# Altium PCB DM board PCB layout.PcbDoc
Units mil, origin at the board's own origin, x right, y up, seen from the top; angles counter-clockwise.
Board outline 4730 x 3600 mil, 4 copper layers (Top Layer, InternalPlane1, InternalPlane2, Bottom Layer); 96 components, 92 nets, 343 pads, 111 vias.
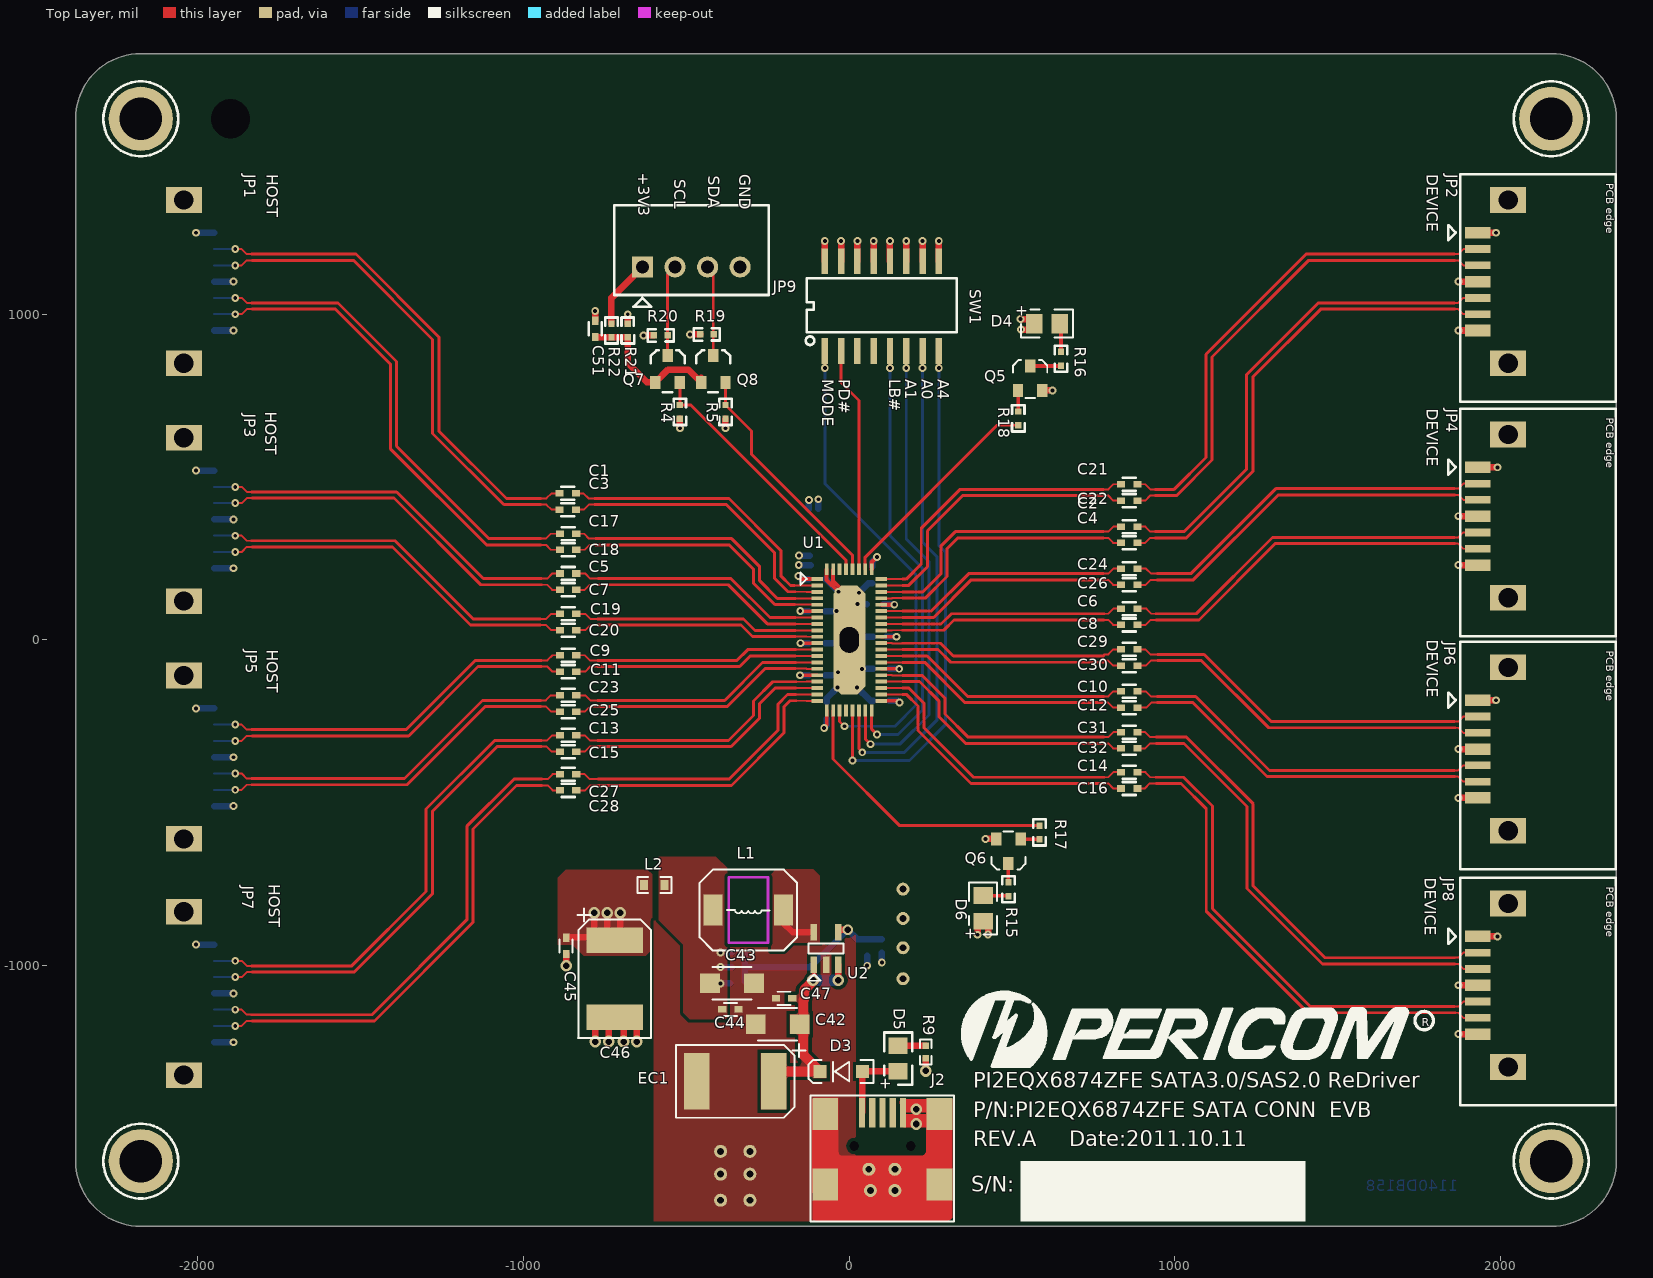
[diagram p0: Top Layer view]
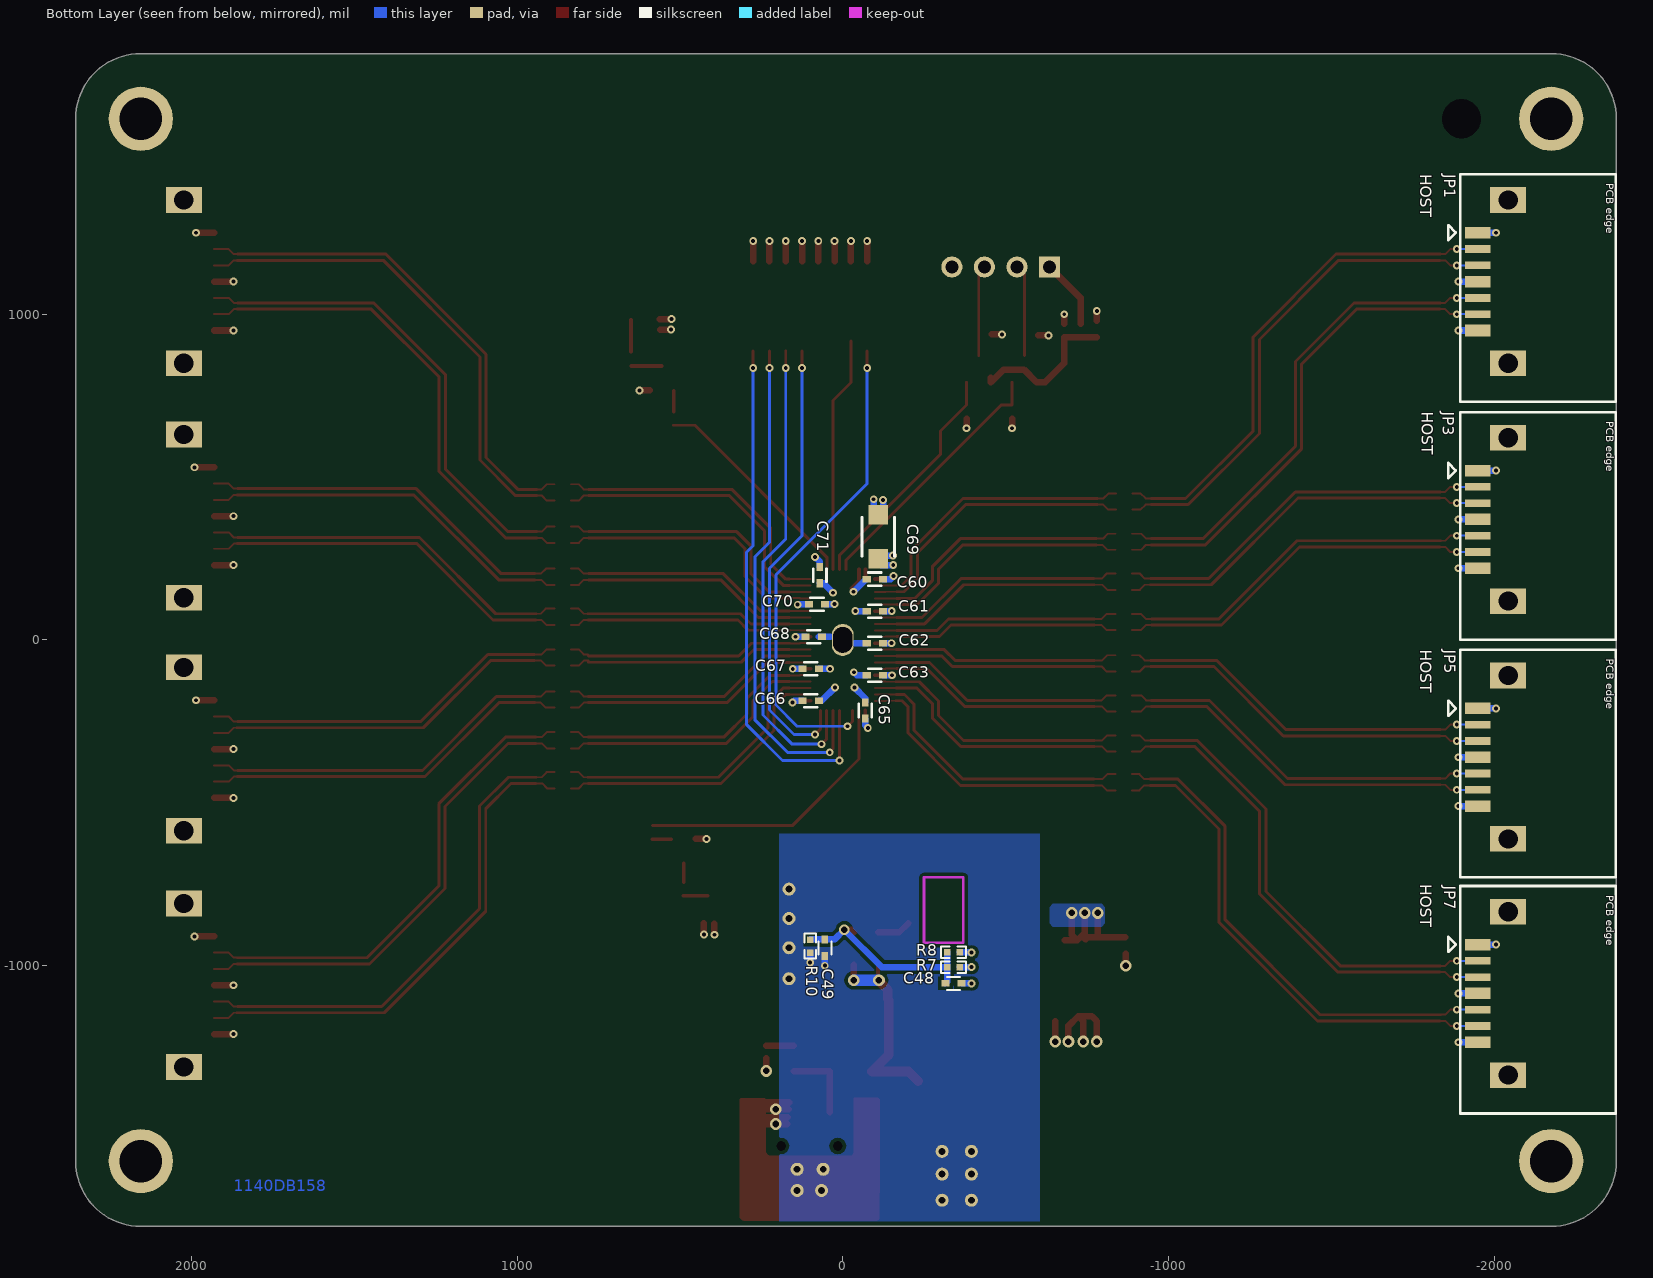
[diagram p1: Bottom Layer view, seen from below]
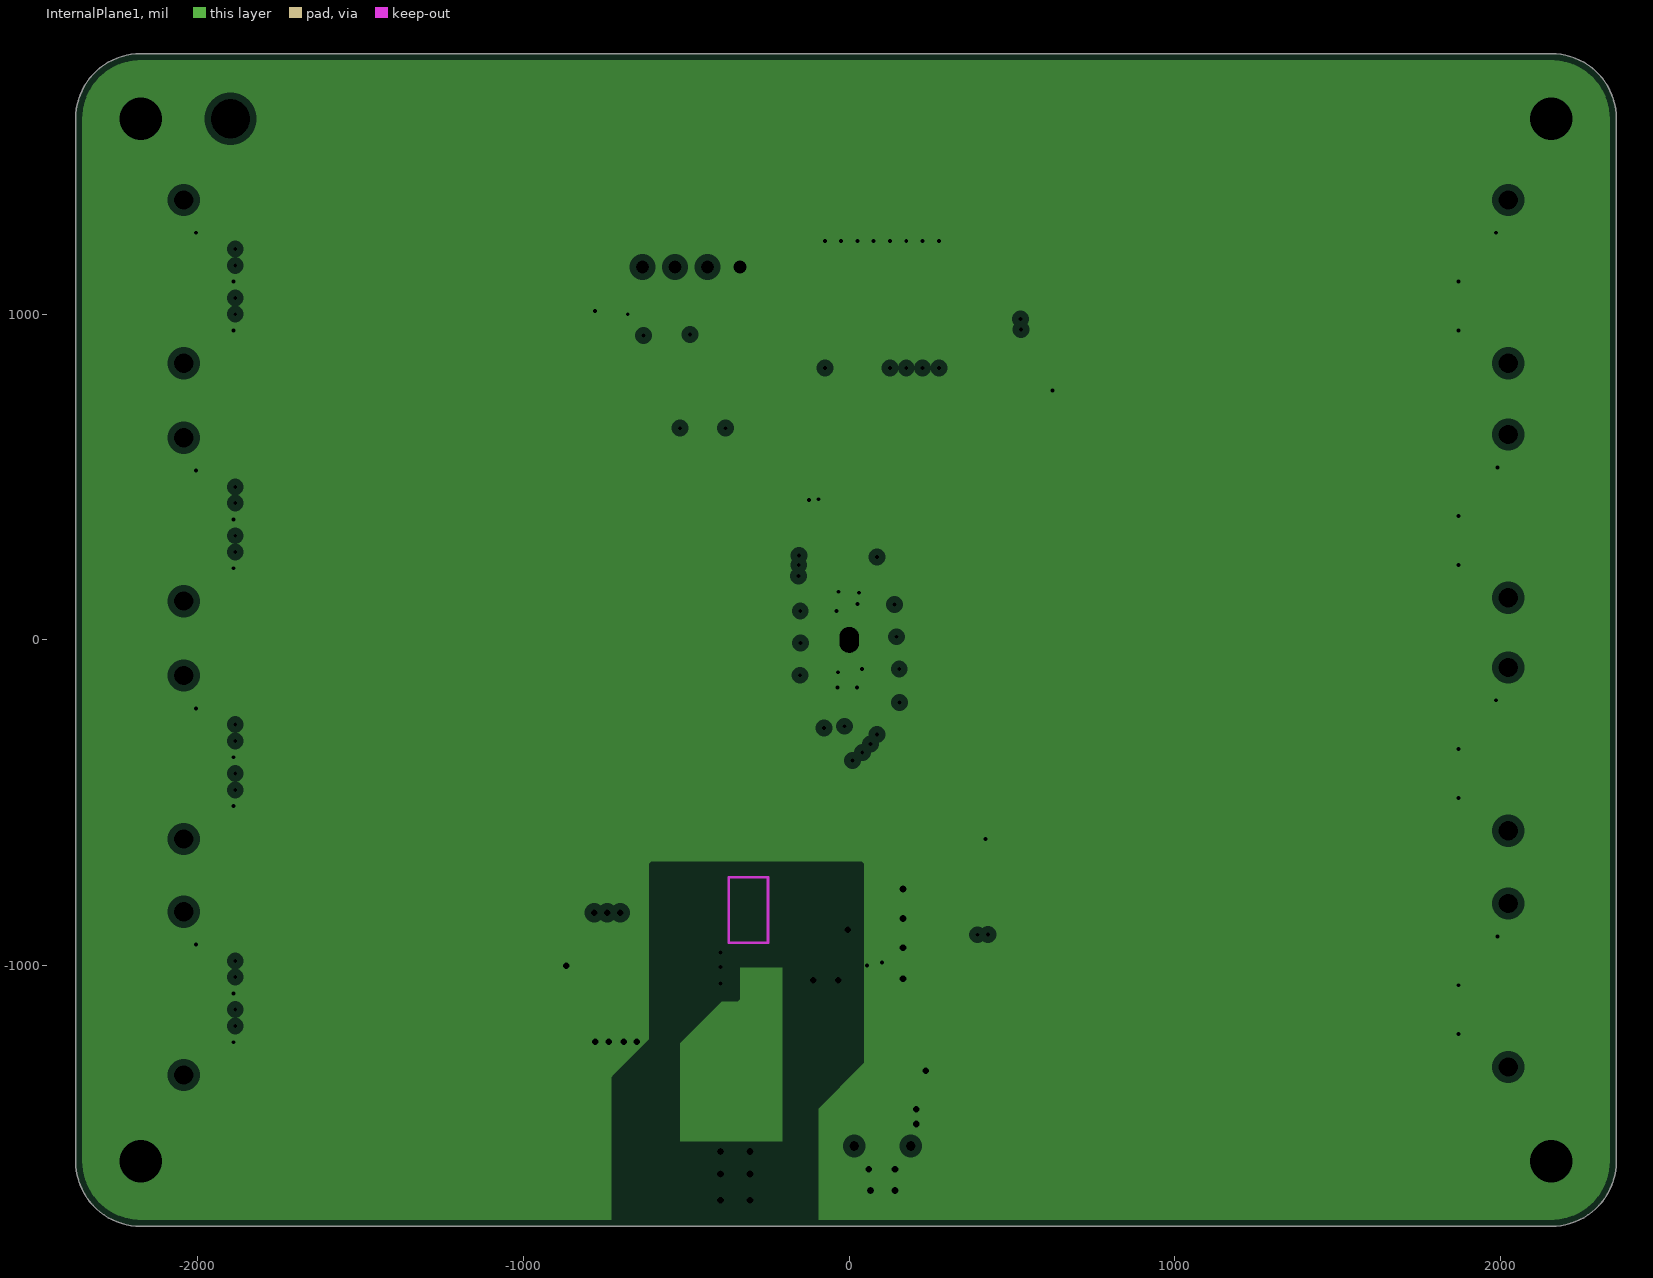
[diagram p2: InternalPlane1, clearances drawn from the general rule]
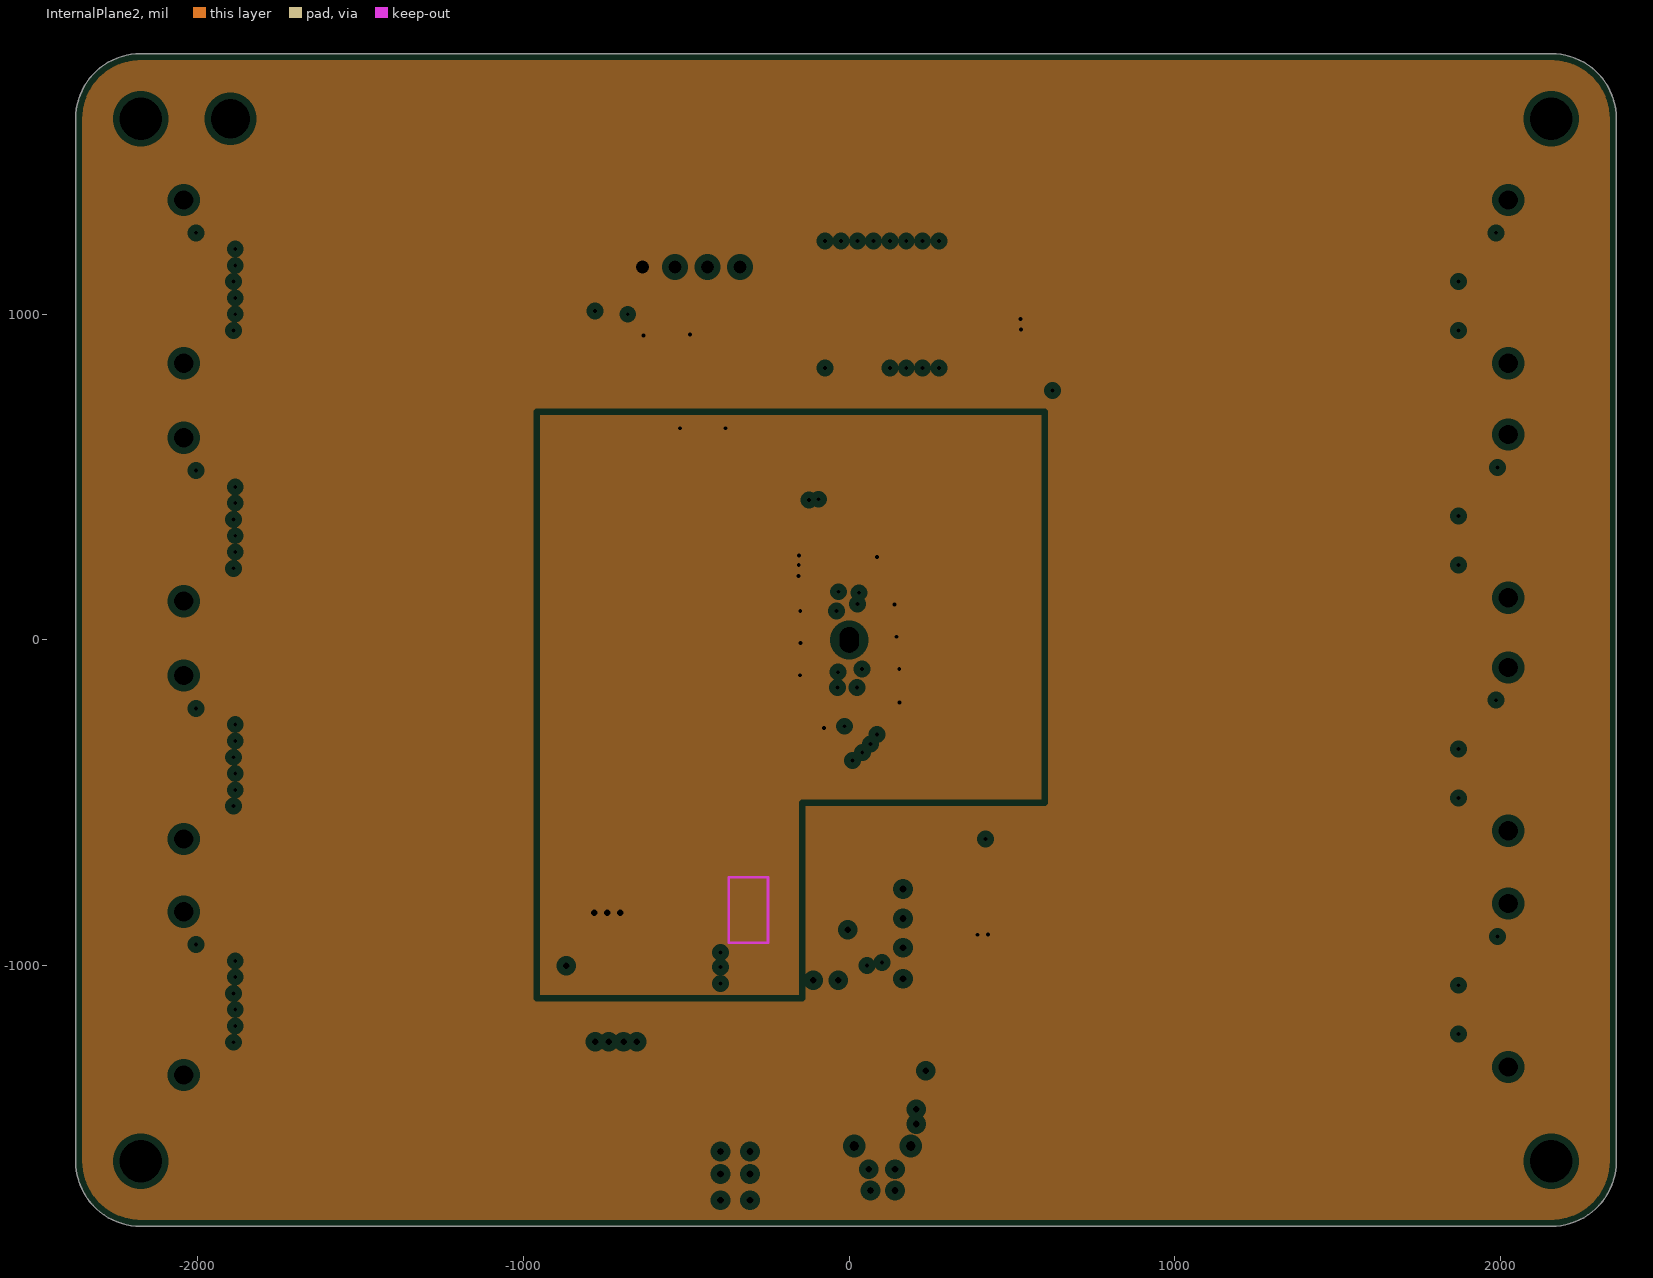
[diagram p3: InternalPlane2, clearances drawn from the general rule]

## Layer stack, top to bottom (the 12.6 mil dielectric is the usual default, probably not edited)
Top Layer: signal copper 1.4
Dielectric: core 12.6, FR-4, Dk 4.8
InternalPlane1: plane copper 1.4, net GND
Dielectric: prepreg 12.6, FR-4, Dk 4.8
InternalPlane2: plane copper 1.4, net +3V3
Dielectric: core 12.6, FR-4, Dk 4.8
Bottom Layer: signal copper 1.4

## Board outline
-2175,-1800 2155,-1800 ccw(c2155,-1600) 2355,-1600 2355,1600 ccw(c2155,1600) 2155,1800 -2175,1800 ccw(c-2175,1600) -2375,1600 -2375,-1600 ccw(c-2175,-1600)

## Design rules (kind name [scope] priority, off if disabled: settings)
Clearance [All] p1: gap=5
ComponentClearance [All] p1: gap=0 collisioncheckmode=3 verticalgap=0
DiffPairsRouting [All] p1: maxlimit=10 minlimit=10 mostfreqgap=10 maxuncoupledlength=500
HoleSize [All] p1: absolutevalues=TRUE maxlimit=500 minlimit=1 maxpercent=80.000 minpercent=20.000
PlaneClearance [All] p1: clearance=20
PlaneConnect [All] p1: planeconnectstyle=Direct reliefexpansion=20 reliefentries=4 reliefconductorwidth=10 reliefairgap=10
PolygonConnect [All] p1: connectstyle=Direct reliefconductorwidth=10 reliefentries=4 polygonreliefangle="90 Angle"
RoomDefinition "PI2EQX6874ZFE TestBoard" [InComponentClass('PI2EQX6874ZFE TestBoard')] p1: confinementstyle=ConfineIn formatcopy=TRUE lockcomponents=FALSE outline -3785,-2755 7974.61,-2755 7974.61,2490 -3785,2490
RoutingVias [All] p1: holewidth=28 width=50 viastyle="Through Hole" minholewidth=8 minwidth=10 maxholewidth=28 maxwidth=50
SolderMaskExpansion [All] p1: expansion=4
TestPointUsage [All] p1: valid=0 allowmultiple=FALSE
Testpoint [All] p1: side=15 testpointundercomponent=TRUE minsize=40 maxsize=100 preferedsize=60 minholesize=0 maxholesize=40 preferedholesize=32 testpointgrid=1 style=1023 order=0-112345678
Width [All] p1: maxlimit=160 minlimit=6 preferedwidth=10
14 further rules are at their usual default settings.

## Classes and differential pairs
differential pair NewDifferentialPair24: +B3TX_P -B3TX_N
differential pair NewDifferentialPair23: +B3RX_P -B3RX_N
differential pair NewDifferentialPair22: +B2TX_P -B2TX_N
differential pair NewDifferentialPair21: +B2RX_P -B2RX_N
differential pair NewDifferentialPair20: +B1TX_P -B1TX_N
differential pair NewDifferentialPair19: +B1RX_P -B1RX_N
differential pair NewDifferentialPair18: +B0TX_P -B0TX_N
differential pair NewDifferentialPair17: +B0RX_P -B0RX_N
differential pair NewDifferentialPair8: +A3TX_P -A3TX_N
differential pair NewDifferentialPair7: +A3RX_P -A3RX_N
differential pair NewDifferentialPair6: +A2TX_P -A2TX_N
differential pair NewDifferentialPair5: +A2RX_P -A2RX_N
differential pair NewDifferentialPair4: +A1TX_P -A1TX_N
differential pair NewDifferentialPair3: +A1RX_P -A1RX_N
differential pair NewDifferentialPair2: +A0TX_P -A0TX_N
differential pair NewDifferentialPair1: +A0RX_P -A0RX_N
differential pair NewDifferentialPair33: +A0RXC_N -A0RXC_P
differential pair NewDifferentialPair34: +A0TXC_N -A0TXC_P
differential pair NewDifferentialPair35: +A1RXC_N -A1RXC_P
differential pair NewDifferentialPair36: +A1TXC_N -A1TXC_P
differential pair NewDifferentialPair37: +A2RXC_N -A2RXC_P
differential pair NewDifferentialPair38: +A2TXC_N -A2TXC_P
differential pair NewDifferentialPair39: +A3RXC_N -A3RXC_P
differential pair NewDifferentialPair40: +A3TXC_N -A3TXC_P
differential pair NewDifferentialPair41: +B0RXC_N -B0RXC_P
differential pair NewDifferentialPair42: +B0TXC_N -B0TXC_P
differential pair NewDifferentialPair43: +B1RXC_N -B1RXC_P
differential pair NewDifferentialPair44: +B1TXC_N -B1TXC_P
differential pair NewDifferentialPair45: +B2RXC_N -B2RXC_P
differential pair NewDifferentialPair46: +B2TXC_N -B2TXC_P
differential pair NewDifferentialPair9: +B3RXC_N -B3RXC_P
differential pair NewDifferentialPair10: +B3TXC_N -B3TXC_P

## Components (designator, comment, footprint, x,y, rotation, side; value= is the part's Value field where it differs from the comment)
C1 "10n" CC_0402 -864,450 r0 top
C2 "10n" CC_0402 859.5,348 r0 top
C3 "10n" CC_0402 -864,400 r0 top
C4 "10n" CC_0402 859.5,298 r0 top
C5 "10n" CC_0402 -863,204 r0 top
C6 "10n" CC_0402 859.5,96 r0 top
C7 "10n" CC_0402 -863,154 r0 top
C8 "10n" CC_0402 859.5,46 r0 top
C9 "10n" CC_0402 -863,-47 r0 top
C10 "10n" CC_0402 859.5,-158 r0 top
C11 "10n" CC_0402 -863,-97 r0 top
C12 "10n" CC_0402 859.5,-208 r0 top
C13 "10n" CC_0402 -863,-293 r0 top
C14 "10n" CC_0402 859.5,-406 r0 top
C15 "10n" CC_0402 -863,-343 r0 top
C16 "10n" CC_0402 859.5,-456 r0 top
C17 "10n" CC_0402 -863,326 r0 top
C18 "10n" CC_0402 -863,277 r0 top
C19 "10n" CC_0402 -863,80 r0 top
C20 "10n" CC_0402 -863,30 r0 top
C21 "10n" CC_0402 859.5,478 r0 top
C22 "10n" CC_0402 859.5,428 r0 top
C23 "10n" CC_0402 -863,-170 r0 top
C24 "10n" CC_0402 859.5,219 r0 top
C25 "10n" CC_0402 -863,-220 r0 top
C26 "10n" CC_0402 859.5,169 r0 top
C27 "10n" CC_0402 -863,-412 r0 top
C28 "10n" CC_0402 -863,-462 r0 top
C29 "10n" CC_0402 859.5,-29 r0 top
C30 "10n" CC_0402 859.5,-79 r0 top
C31 "10n" CC_0402 859.5,-283 r0 top
C32 "10n" CC_0402 859.5,-333 r0 top
C42 "4.7u" CAP@CC_1206 -220,-1179.33 r180 top
C43 "10u" CAP@CC_1206 -360,-1054.33 r0 top
C44 "0.1u" CAP@CC_0402 -365,-1134.33 r0 top
C45 "0.1u" CAP@CC_0402 -869,-939 r90 top
C46 "100u" CAP@CT_7343 -720,-1040 r90 top locked
C47 "0.1u" CAP@CC_0402 -200,-1100 r180 top
C48 "12pF" CAP@CC_0402 -340,-1054.33 r0 bottom
C49 "NP" CAP@CC_0402 55,-945 r270 bottom
C51 "100n" CAP@CC_0402 -780,955 r90 top
C60 "0.1u" CC_0402 -98.82,187.01 r0 bottom
C61 "0.1u" CC_0402 -98.82,88.58 r0 bottom
C62 "0.1u" CC_0402 -98.82,-9.84 r0 bottom
C63 "0.1u" CC_0402 -98.82,-108.27 r0 bottom
C65 "0.1u" CC_0402 -69.29,-216.54 r90 bottom
C66 "0.1u" CC_0402 98.03,-187.01 r180 bottom
C67 "0.1u" CC_0402 98.03,-88.58 r180 bottom
C68 "0.1u" CC_0402 89,10 r180 bottom
C69 "10u_1206" CC_1206 -109,317 r90 bottom
C70 "0.1u" CC_0402 79,110 r180 bottom (schematic designator C68)
C71 "0.1u" CC_0402 70,199 r270 bottom (schematic designator C68)
D3 "B0520LW" D_SOD_123 -25,-1325 r180 top
D4 "LED" LED@LD0805 607,971 r0 top
D5 "LED" LED@LD0805 150,-1285 r90 top
D6 "LED" LED@LD0805 411,-824 r90 top
EC1 "100uF" CAP@CT_7343 -350,-1355 r0 top
J2 "Mini USB 2.0 Type B Female" USB_B_MINI@USB_B_MINI 102,-1760 r90 top (schematic designator J1)
JP1 "CON_SATA_SMT" CON_SATA_SMT -1950,950 r90 bottom
JP2 "CON_SATA_SMT" CON_SATA_SMT 1930,950 r90 top
JP3 "CON_SATA_SMT" CON_SATA_SMT -1950,220 r90 bottom
JP4 "CON_SATA_SMT" CON_SATA_SMT 1930,230 r90 top
JP5 "CON_SATA_SMT" CON_SATA_SMT -1950,-510 r90 bottom
JP6 "CON_SATA_SMT" CON_SATA_SMT 1930,-485 r90 top
JP7 "CON_SATA_SMT" CON_SATA_SMT -1950,-1235 r90 bottom
JP8 "CON_SATA_SMT" CON_SATA_SMT 1930,-1210 r90 top
JP9 "CONN_4P" "I2C Device" -635,1145 r0 top
L1 "2.2uH" INDUCTORS-Power -310,-829.33 r180 top
L2 "BL1005LL680" FB@LF0603 -599,-752 r180 top
Q5 "MMBT3904" Q(NPN)@SOT23 518,766 r0 top
Q6 "MMBT3904" Q(NPN)@SOT23 526,-611 r180 top
Q7 "2SK3018@SOT-23" SOT-23 -595,795 r0 top
Q8 "2SK3018@SOT-23" SOT-23 -455,795 r0 top
R4 "4.7K" RES@R_0402#1 -520,700 r90 top
R5 "4.7K" RES@R_0402#1 -380,700 r90 top
R7 "280k" RES@R_0402#2 -340,-1004.33 r0 bottom
R8 "680k" RES@R_0402#2 -340,-959.33 r0 bottom
R9 "510" RES@R_0402#2 235,-1265 r90 top
R10 "200K" RES@R_0402#2 100,-940 r270 bottom
R15 "470" R_0402 489,-765 r270 top
R16 "470" R_0402 650,863 r90 top
R17 "470" R_0402 584,-591 r270 top
R18 "470" R_0402 519,680 r90 top
R19 "10k" R_0402 -437,938 r0 top
R20 "10k" R_0402 -579,935 r0 top
R21 "27k" RES@R_0402#1 -680,950 r90 top
R22 "10k" RES@R_0402#1 -730,950 r90 top
SW1 "CHS-08TA" CHS-08TA@CHS-08TA 100,1025 r0 top
U1 "PI2EQX6874ZFE@TQFN56" TQFN56 0,0 r90 top locked
U2 "LM3674" SOT23-5 -71,-947.33 r180 top locked
? "" "Lable Hole" -1900,1600 r0 top
? "" PSC_LOGO3 380,-1295 r0 top
? "" HOLE5M3M3 2155,-1600 r0 top
? "" HOLE5M3M3 -2175,-1600 r0 top
? "" HOLE5M3M3 -2175,1600 r0 top
? "" HOLE5M3M3 2155,1600 r0 top

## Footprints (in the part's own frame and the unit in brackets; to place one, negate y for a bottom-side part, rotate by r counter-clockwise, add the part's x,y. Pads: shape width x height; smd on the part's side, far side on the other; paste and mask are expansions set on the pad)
CAP@CC_0402 [mil]
  rect 25x20 smd: 1(-25,0) 2(25,0)
  silkscreen extent -20,-20 20,20
CAP@CC_1206 [mil]
  rect 60x60 smd: 1(-67.5,0) 2(67.5,0)
  silkscreen extent -60,-50 60,50
CAP@CT_7343 [mm]
  rect 2x4.4 smd: 1(3,0) 2(-3,0)
  silkscreen extent -4.63,-2.84 5.48,2.9
CC_0402 [mil]
  rect 25x20 smd: 1(-25,0) 2(25,0)
  silkscreen extent -20,-20 20,20
CC_1206 [mil]
  rect 60x60 smd: 1(-67.5,0) 2(67.5,0)
  silkscreen extent -60,-50 60,50
CHS-08TA@CHS-08TA [mm] "CHS-08TA"
  rect 0.5x2 smd: 1(-4.445,-3.5) 2(-3.175,-3.5) 3(-1.905,-3.5) 4(-0.635,-3.5) 5(0.635,-3.5) 6(1.905,-3.5) 7(3.175,-3.5) 8(4.445,-3.5) 9(4.445,3.5) 10(3.175,3.5) 11(1.905,3.5) 12(0.635,3.5) 13(-0.635,3.5) 14(-1.905,3.5) 15(-3.175,3.5) 16(-4.445,3.5)
  silkscreen extent -5.93,-3.04 5.85,2.16
CON_SATA_SMT [mm] "SATA7PIN, BODY 17.74x11.9, 7x1, PITCH 1.27"
  rect 2x2.8 hole 1.5: 0(-2.56,-2.36) 0(10.18,-2.36)
  rect 0.9x2 smd: 1(7.62,0.003) 4(3.81,0.003) 7(0,0.003)
  rect 0.6x2 smd: 2(6.35,0.003) 3(5.08,0.003) 5(2.54,0.003) 6(1.27,0.003)
  silkscreen extent -5.56,-10.76 12.18,2.31
D_SOD_123 [mil]
  rect 40x40 smd: 1(-65,0) 2(65,0)
  silkscreen extent -100,-35 100,35
FB@LF0603 [mm]
  rect 0.635x0.8 smd: 1(-0.8,0) 2(0.8,0)
  silkscreen extent -1.34,-0.62 1.3,0.62
HOLE5M3M3 [mm] "HOLE, Plated"
  round 5 hole 3.3: 0(0,0)
  silkscreen extent -2.92,-2.92 2.92,2.92
"I2C Device" [mil]
  rect 65x65 hole 40: 1(0,0)
  round 65 hole 40: 2(100,0) 3(200,0) 4(300,0)
  silkscreen extent -87,-86 387,190
INDUCTORS-Power [mm]
  rect 1.5x2.4 smd: 1(-2.75,0) 2(2.75,0)
  Keep-Out Layer lines w0.203: 1.53,2.55 -1.54,2.55 -1.54,-2.55 1.53,-2.55 1.53,2.55
  silkscreen extent -3.8,-3.15 3.8,3.15
"Lable Hole" [mil]
  round 0 hole 120 unplated: ""(0,0)
LED@LD0805 [mm] "Chip Resistor; Body 2 x 1.3 mm (LxW typ)"
  rect 1.3x1.5 smd: 1(-1,0) 2(1,0)
  silkscreen extent -2.03,-1.09 2.03,1.09
PSC_LOGO3 [mil]
  silkscreen extent -32,-15 1413,214
Q(NPN)@SOT23 [mil]
  rect 32.01x40 smd: B(0,0) C(37.48,75) E(75,0)
  silkscreen extent -15,-24 90,94
R_0402 [mm]
  rect 0.5x0.5 smd: 1(-0.532,-0.001) 2(0.54,-0.001)
  silkscreen extent -1.02,-0.49 1.02,0.49
RES@R_0402#1 [mm]
  rect 0.5x0.5 smd: 1(-0.532,-0.001) 2(0.54,-0.001)
  silkscreen extent -1.02,-0.49 1.02,0.49
RES@R_0402#2 [mm]
  rect 0.5x0.5 smd: 1(-0.5,0) 2(0.5,0)
  silkscreen extent -0.97,-0.45 0.97,0.45
SOT23-5 [mil]
  rect 20x50 smd: 1(37.5,50) 2(0,50) 3(-37.5,50) 4(-37.5,-50) 5(37.5,-50)
  silkscreen extent -54,-15 57,99
SOT-23 [mil]
  rect 32.01x40 smd: D(37.48,78.74) G(0,-3.94) S(75,-3.94)
  silkscreen extent -15,-34 90,94
TQFN56 [mm]
  rect 0.3x0.9 smd: 1(4.75,2.5) 2(4.25,2.5) 3(3.75,2.5) 4(3.25,2.5) 5(2.75,2.5) 6(2.25,2.5) 7(1.75,2.5) 8(1.25,2.5) 9(0.75,2.5) 10(0.25,2.5) 11(-0.25,2.5) 12(-0.75,2.5) 13(-1.25,2.5) 14(-1.75,2.5) 15(-2.25,2.5) 16(-2.75,2.5) 17(-3.25,2.5) 18(-3.75,2.5) 19(-4.25,2.5) 20(-4.75,2.5) 29(-4.75,-2.5) 30(-4.25,-2.5) 31(-3.75,-2.5) 32(-3.25,-2.5) 33(-2.75,-2.5) 34(-2.25,-2.5) 35(-1.75,-2.5) 36(-1.25,-2.5) 37(-0.75,-2.5) 38(-0.25,-2.5) 39(0.25,-2.5) 40(0.75,-2.5) 41(1.25,-2.5) 42(1.75,-2.5) 43(2.25,-2.5) 44(2.75,-2.5) 45(3.25,-2.5) 46(3.75,-2.5) 47(4.25,-2.5) 48(4.75,-2.5)
  rect 0.9x0.3 smd: 21(-5.5,1.75) 22(-5.5,1.25) 23(-5.5,0.75) 24(-5.5,0.25) 25(-5.5,-0.25) 26(-5.5,-0.75) 27(-5.5,-1.25) 28(-5.5,-1.75) 49(5.5,-1.75) 50(5.5,-1.25) 51(5.5,-0.75) 52(5.5,-0.25) 53(5.5,0.25) 54(5.5,0.75) 55(5.5,1.25) 56(5.5,1.75)
  oval 2.5x1.7 hole 1.5 slot 2 at 0 deg: 57(0,0)
  oct 8.5x2.5 smd: 57(0,-0.01)
  silkscreen extent 4.27,3.31 5.27,3.81
USB_B_MINI@USB_B_MINI [mm]
  rect 2.3x0.5 smd: 1(7.85,1.6) 2(7.85,0.8) 3(7.85,0) 4(7.85,-0.8) 5(7.85,-1.6)
  rect 2.5x2 smd: 5(2.25,4.45) 5(2.25,-4.45) 5(7.75,-4.45) 5(7.75,4.45)
  round 0 hole 0.762 unplated: 10(5.25,-2.2) 11(5.25,2.2)
  Top Layer region: 1.58,5.45 -0.35,5.45 -0.438,5.432 -0.513,5.383 -0.562,5.308 -0.58,5.22 -0.58,5.22 -0.58,-5.09 -0.553,-5.224 -0.477,-5.337 -0.364,-5.413 -0.23,-5.44 -0.23,-5.44 8.81,-5.44 8.875,-5.427 8.93,-5.39 8.967,-5.335 8.98,-5.27 8.98,-5.27 8.98,-3.59 8.968,-3.529 8.933,-3.477 8.881,-3.442 8.82,-3.43 8.82,-3.43 4.93,-3.43 4.758,-3.396 4.612,-3.298 4.514,-3.152 4.48,-2.98 4.48,-2.98 4.48,3.17 4.5,3.269 4.556,3.354 4.641,3.41 4.74,3.43 4.74,3.43 8.93,3.43 8.964,3.437 8.994,3.456 9.013,3.486 9.02,3.52 9.02,3.52 9.02,5.26 9.004,5.34 8.958,5.408 8.89,5.454 8.81,5.47 8.81,5.47 1.6,5.47 1.592,5.468 1.586,5.464 1.582,5.458 1.58,5.45
  silkscreen extent -0.65,-5.59 9.19,5.6

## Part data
C1 C2 C3 C4 C5 C6 C7 C8 C9 C10 C11 C12 C13 C14 C15 C16 C17 C18 C19 C20 C21 C22 C23 C24 C25 C26 C27 C28 C29 C30 C31 C32 C51 C60 C61 C62 C63 C65 C66 C67 C68 C70 C71: library part "CHIP CAP0402_Dup1"
C42 C43: library part "CHIP CAP1206"
C44 C47 C48 C49: library part "CHIP CAP0402"
C45: library part "CHIP CAP_11"
C46: library part ECAP@CT_0
C69: library part C_10u_1206
D3: library part 1N5817M/CYL
D4 D6: library part LED_3
D5: library part LED@LD0805_0
EC1: library part ECAP@CT_7343
J2: library part "USB 2_0.0 Mini B Female"
JP1 JP2: library part CON_SAS_36PIN
JP3 JP5 JP6 JP7 JP8: library part CON_SATA_SMT_Dup1
JP4: library part CONN_4P
L1: library part INDUCTOR@INDUCTOR1_9
L2: library part "FB _0603"
Q5 Q6: library part "T NPN BEC_0"
R4 R5 R19 R20 R21 R22: library part "CHIP RES0402_0_Dup1"
R7 R8 R10: library part "CHIP RES0402_2"
R9: library part "CHIP RES0402_0"
R15 R16 R17 R18: library part "CHIP RES0402_1"
U1: library part PI2EQX6874ZFE@TQFN56_1
U2: library part LM3674@SOT23-5

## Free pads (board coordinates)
  round 40 hole 21: 0(-395,-1720) 0(-395,-1640) 0(-395,-1570) 0(-305,-1720) 0(-305,-1640) 0(-305,-1570) 0(60,-1625) 0(65,-1690) 0(140,-1690) 0(140,-1625) 0(165,-1040) 0(165,-945) 0(165,-855) 0(165,-765)

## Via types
v1: diameter 24, hole 12, Top Layer to Bottom Layer, tented both sides, 97 vias
v2: diameter 36, hole 20, Top Layer to Bottom Layer, tented both sides, 13 vias
v3: diameter 32, hole 20, Top Layer to Bottom Layer, tented both sides, 1 vias

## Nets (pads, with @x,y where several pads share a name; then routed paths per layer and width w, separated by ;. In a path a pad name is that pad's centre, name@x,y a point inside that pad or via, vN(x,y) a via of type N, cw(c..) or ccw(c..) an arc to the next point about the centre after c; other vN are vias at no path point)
+1V2: C45.2 C46.1 C60.1 C61.1 C62.1 C63.1 C65.1 C66.1 C67.1 C68.1 C69.1 C70.1 C71.1 L2.2 R4.1 R5.1 U1.1 U1.6 U1.11 U1.16 U1.21 U1.29 U1.34 U1.39 U1.44 U1.49 | length 1396.6
  Top Layer w11: v1(-156,196) -147.01,187.01 U1.1@-98.82,187.01 ; v1(-150.73,-108.27) U1.16@-98.82,-108.27 ; v1(-150.42,88.58) U1.6@-98.82,88.58 ; v1(-149.24,-9.84) U1.11@-98.82,-9.84 ; v1(-77,-270) -69.29,-262.29 U1.21@-69.29,-216.54 ; U1.29@98.03,-187.01 149.01,-187.01 v1(154,-192) ; U1.34@98.03,-88.58 v1(153.42,-88.58) ; U1.39@98.03,9.84 v1(145,9.84)
  Top Layer w13: U1.49 68.9,238.9 v1(85,255) ; U1.44 v1(138.27,108.27)
  Top Layer w20: C45.2@-868,-913 C46.1@-728.89,-913 ; v2(-783,-838) -783,-908 C46.1@-778,-913 ; C46.1@-746.5,-919.5 C46.1@-744,-917 ; v2(-743,-838) -743,-898.89 C46.1 ; v2(-703,-838) -703,-904.89 C46.1 ; C46.1@-681.89,-921.89 C46.1 ; v1(-519.97,650.03) R4.1 ; v1(-379.97,650.03) R5.1
  Bottom Layer w20: v1(-156,196) -147.01,187.01 C60.1 ; v1(-155,230) C69.1@-119,230 ; v1(-154,259) C69.1@-121,259 ; v1(-150.73,-108.27) C63.1 ; v1(-150.42,88.58) C61.1 ; v1(-149.24,-9.84) C62.1 ; v1(-77,-270) -69.29,-262.29 C65.1 ; C71.1 70,240 v1(85,255) ; C70.1 v1@136.54,110 ; C68.1 v1@144.84,10 ; C66.1 149.01,-187.01 v1(154,-192) ; C67.1 v1(153.42,-88.58)
+3V3: D4.1 D6.1 JP9.1 R19.1 R20.1 R22.2 | length 413.1
  Top Layer w20: R22.2 -729.97,1050.03 JP9.1 ; v1(-631.97,934.97) R20.1 ; v1(-488.97,937.97) R19.1 ; v1(394,-905) D6.1@394,-871 ; v1(426,-904) D6.1@426,-869 ; v1(526,985) D4.1@561,985 ; v1(527,953) D4.1@560,953
+5.0V: C42.1 C47.1 D3.2 EC1.1 U2.1 U2.3 | length 639.1
  Top Layer w12: v2@-111,-1047.33 -108.5,-1044.83 U2.1
  Top Layer w20: v2(-33.5,-1044.83) U2.3
  Top Layer w30: EC1.1 -201.89,-1325 D3.2 -141,-1274 -141,-1107.33 ; -141,-1104.83 -138.5,-1102.33 -138.5,-1074.83 v2@-111,-1047.33
  Bottom Layer w36: v2(-111,-1044.83) v2(-33.5,-1044.83)
A0: SW1.7 U1.26 | length 1555.1
  Top Layer w9: U1.26 29.53,-334.53 v1(40,-345) ; v1(225,835) SW1.7
  Bottom Layer w9: v1(40,-345) 170,-345 270,-245 270,255 225,300 v1(225,835)
A0RX_N: C3.1 JP1.3 | length 1551.7
  Top Layer w6: v1(-1885,1150) -1865,1150 -1849.5,1165.5 -1833.73,1165.5 ; -944.82,415.5 -929.5,415.5 -914,400 C3.1
  Top Layer w9: -1833.73,1165.5 -1522.37,1165.5 -1279,922.13 -1279,634 -1060.5,415.5 -946.27,415.5
  Bottom Layer w6: JP1.3 v1(-1885,1150)
A0RX_P: C1.1 JP1.2 | length 1553.2
  Top Layer w6: v1(-1885,1200) -1865,1200 -1849.5,1184.5 -1834.84,1184.5 ; -946.27,434.5 -929.5,434.5 -914,450 C1.1
  Top Layer w9: -1834.84,1184.5 -1514.5,1184.5 -1260,930 -1260,641.87 -1052.63,434.5 -946.27,434.5
  Bottom Layer w6: JP1.2 v1(-1885,1200)
A0RXC_N: C3.2 U1.3 | length 903.3
  Top Layer w6: C3.2 -815,400 -799.5,415.5 -782,415.5 ; -165.91,147.98 -131.88,147.98 -131.54,147.64 U1.3@-98.82,147.64
  Top Layer w9: -782,415.5 -377.37,415.5 -229,267.13 -229,189 -187.98,147.98 -165.91,147.98
A0RXC_P: C1.2 U1.2 | length 903.3
  Top Layer w6: C1.2 -816,450 -800.5,434.5 -782,434.5 ; -167.46,166.98 -131.88,166.98 -131.54,167.32 U1.2@-98.82,167.32
  Top Layer w9: -782,434.5 -369.5,434.5 -210,275 -210,196.87 -180.11,166.98 -167.46,166.98
A0TX_N: C22.2 JP2.3 | length 1541.5
  Top Layer w6: C22.2 908,428 923.5,443.5 937.12,443.5 ; 1859.11,1165.5 1869.5,1165.5 1885,1150 JP2.3
  Top Layer w9: 938.57,443.5 1005.37,443.5 1114,552.13 1114,869 1410.5,1165.5 1859.11,1165.5
A0TX_P: C21.2 JP2.2 | length 1542.9
  Top Layer w6: C21.2 909,478 924.5,462.5 938.57,462.5 ; 1858.03,1184.5 1869.5,1184.5 1885,1200 JP2.2
  Top Layer w9: 938.57,462.5 997.5,462.5 1095,560 1095,876.87 1402.63,1184.5 1858.03,1184.5
A0TXC_N: C22.1 U1.47 | length 921.3
  Top Layer w6: U1.47 131.14,167.32 131.48,167.67 162.96,167.67 ; 780.43,443.5 794.5,443.5 810,428 C22.1
  Top Layer w9: 162.96,167.67 182.67,167.67 240,225 240,335 348.5,443.5 780.43,443.5
A0TXC_P: C21.1 U1.48 | length 919.9
  Top Layer w6: U1.48 131.14,187.01 131.48,186.67 162.96,186.67 ; 781.88,462.5 795.5,462.5 811,478 C21.1
  Top Layer w9: 162.96,186.67 174.79,186.67 221,232.87 221,342.87 340.63,462.5 780.43,462.5
A1: SW1.6 U1.27 | length 1473.5
  Top Layer w9: U1.27 49.21,-304.21 v1(65,-320) ; v1(175,835) SW1.6
  Bottom Layer w9: v1(65,-320) 155,-320 245,-230 245,240 175,310 v1(175,835)
A1RX_N: C7.1 JP3.3 | length 1185.6
  Top Layer w6: v1(-1885,420) -1865,420 -1849.5,435.5 -1833.73,435.5 ; -945.54,169.5 -927.5,169.5 -912,154 C7.1
  Top Layer w9: -1833.73,435.5 -1397.37,435.5 -1131.37,169.5 -944.82,169.5
  Bottom Layer w6: JP3.3 v1(-1885,420)
A1RX_P: C5.1 JP3.2 | length 1184.9
  Top Layer w6: v1(-1885,470) -1865,470 -1849.5,454.5 -1834.84,454.5 ; -944.82,188.5 -927.5,188.5 -912,204 C5.1
  Top Layer w9: -1834.84,454.5 -1389.5,454.5 -1123.5,188.5 -944.82,188.5
  Bottom Layer w6: JP3.2 v1(-1885,470)
A1RXC_N: C7.2 U1.8 | length 794.4
  Top Layer w6: C7.2 -812,154 -796.5,169.5 -773,169.5 ; -164.75,49.56 -131.88,49.56 -131.54,49.21 U1.8@-98.82,49.21
  Top Layer w9: -772,169.5 -371.37,169.5 -251.43,49.55 -164.75,49.56
A1RXC_P: C5.2 U1.7 | length 795.4
  Top Layer w6: C5.2 -811,204 -795.5,188.5 -772,188.5 ; -165.14,68.56 -131.88,68.56 -131.54,68.9 U1.7@-98.82,68.9
  Top Layer w9: -772,188.5 -363.5,188.5 -243.56,68.56 -165.14,68.56
A1TX_N: C26.2 JP4.3 | length 1167.1
  Top Layer w6: C26.2 910,169 925.5,184.5 945.83,184.5 ; 1859.11,445.5 1869.5,445.5 1885,430 JP4.3
  Top Layer w9: 945.1,184.5 1056.37,184.5 1317.37,445.5 1859.11,445.5
A1TX_P: C24.2 JP4.2 | length 1166.4
  Top Layer w6: C24.2 911,219 926.5,203.5 945.1,203.5 ; 1858.03,464.5 1869.5,464.5 1885,480 JP4.2
  Top Layer w9: 945.1,203.5 1048.5,203.5 1309.5,464.5 1858.03,464.5
A1TXC_N: C26.1 U1.42 | length 790.4
  Top Layer w6: U1.42 131.14,68.9 131.48,69.24 162.96,69.24 ; 780.43,184.5 794.5,184.5 810,169 C26.1
  Top Layer w9: 162.96,69.24 259.24,69.24 374.5,184.5 780.43,184.5
A1TXC_P: C24.1 U1.43 | length 788.9
  Top Layer w6: U1.43 131.14,88.58 131.48,88.24 162.96,88.24 ; 781.88,203.5 795.5,203.5 811,219 C24.1
  Top Layer w9: 162.96,88.24 251.37,88.24 366.63,203.5 780.43,203.5
A2RX_N: C11.1 JP5.3 | length 1163
  Top Layer w6: v1(-1885,-310) -1865,-310 -1849.5,-294.5 -1833.73,-294.5 ; -944.82,-81.5 -926.5,-81.5 -911,-97 C11.1
  Top Layer w9: -1833.73,-294.5 -1352.63,-294.5 -1139.63,-81.5 -944.82,-81.5
  Bottom Layer w6: JP5.3 v1(-1885,-310)
A2RX_P: C9.1 JP5.2 | length 1162.2
  Top Layer w6: v1(-1885,-260) -1865,-260 -1849.5,-275.5 -1834.84,-275.5 ; -944.09,-62.5 -926.5,-62.5 -911,-47 C9.1
  Top Layer w9: -1834.84,-275.5 -1360.5,-275.5 -1147.5,-62.5 -944.82,-62.5
  Bottom Layer w6: JP5.2 v1(-1885,-260)
A2RXC_N: C11.2 U1.13 | length 758.3
  Top Layer w6: C11.2 -811,-97 -795.5,-81.5 -774,-81.5 ; -164.75,-48.87 -99.16,-48.87 U1.13@-98.82,-49.21
  Top Layer w9: -773,-81.5 -336.5,-81.5 -303.87,-48.87 -164.75,-48.87
A2RXC_P: C9.2 U1.12 | length 759.3
  Top Layer w6: C9.2 -812,-47 -796.5,-62.5 -773,-62.5 ; -163.49,-29.87 -131.88,-29.87 -131.54,-29.53 U1.12@-98.82,-29.53
  Top Layer w9: -773,-62.5 -344.37,-62.5 -311.74,-29.87 -163.49,-29.87
A2TX_N: C30.2 JP6.3 | length 1145
  Top Layer w6: C30.2 910,-79 925.5,-63.5 947.28,-63.5 ; 1859.11,-269.5 1869.5,-269.5 1885,-285 JP6.3
  Top Layer w9: 945.83,-63.5 1081.63,-63.5 1287.63,-269.5 1859.11,-269.5
A2TX_P: C29.2 JP6.2 | length 1143.6
  Top Layer w6: C29.2 909,-29 924.5,-44.5 945.83,-44.5 ; 1858.03,-250.5 1869.5,-250.5 1885,-235 JP6.2
  Top Layer w9: 945.83,-44.5 1089.5,-44.5 1295.5,-250.5 1858.03,-250.5
A2TXC_N: C30.1 U1.37 | length 758.9
  Top Layer w6: U1.37 131.14,-29.53 131.48,-29.19 162.96,-29.19 ; 780.43,-63.5 794.5,-63.5 810,-79 C30.1
  Top Layer w9: 162.96,-29.19 272.31,-29.19 311.63,-68.5 780.43,-68.5
A2TXC_P: C29.1 U1.38 | length 757.5
  Top Layer w6: U1.38 131.14,-9.84 131.48,-10.18 162.96,-10.18 ; 781.88,-44.5 795.5,-44.5 811,-29 C29.1
  Top Layer w9: 162.96,-10.18 280.18,-10.18 319.5,-49.5 780.43,-49.5
A3RX_N: C15.1 JP7.3 | length 1509.7
  Top Layer w6: v1(-1885,-1035) -1865,-1035 -1849.5,-1019.5 -1833.73,-1019.5 ; -944.82,-327.5 -929.11,-327.5 -913.61,-343 C15.1
  Top Layer w9: -1833.73,-1019.5 -1519.5,-1019.5 -1280,-780 -1280,-526.87 -1080.63,-327.5 -944.82,-327.5
  Bottom Layer w6: JP7.3 v1(-1885,-1035)
A3RX_P: C13.1 JP7.2 | length 1508.9
  Top Layer w6: v1(-1885,-985) -1865,-985 -1849.5,-1000.5 -1834.84,-1000.5 ; -944.09,-308.5 -927.11,-308.5 -911.61,-293 C13.1
  Top Layer w9: -1834.84,-1000.5 -1527.37,-1000.5 -1299,-772.13 -1299,-519 -1088.5,-308.5 -944.82,-308.5
  Bottom Layer w6: JP7.2 v1(-1885,-985)
A3RXC_N: C15.2 U1.18 | length 846.7
  Top Layer w6: C15.2 -812,-343 -796.5,-327.5 -773,-327.5 ; -164.37,-147.3 -131.88,-147.3 -131.54,-147.64 U1.18@-98.82,-147.64
  Top Layer w9: -773,-327.5 -362.5,-327.5 -275,-240 -275,-195 -227.3,-147.3 -164.37,-147.3
A3RXC_P: C13.2 U1.17 | length 847.7
  Top Layer w6: C13.2 -812,-293 -796.5,-308.5 -772,-308.5 ; -163.6,-128.3 -131.88,-128.3 -131.54,-127.95 U1.17@-98.82,-127.95
  Top Layer w9: -773,-308.5 -370.37,-308.5 -294,-232.13 -294,-187.13 -235.17,-128.3 -163.6,-128.3
A3TX_N: C32.2 JP8.3 | length 1488.4
  Top Layer w6: C32.2 908,-333 923.5,-317.5 943.65,-317.5 ; 1859.11,-994.5 1869.5,-994.5 1885,-1010 JP8.3
  Top Layer w9: 941.47,-317.5 1027.5,-317.5 1221,-511 1221,-762.87 1452.63,-994.5 1859.11,-994.5
A3TX_P: C31.2 JP8.2 | length 1486.2
  Top Layer w6: C31.2 908,-283 923.5,-298.5 941.47,-298.5 ; 1858.03,-975.5 1869.5,-975.5 1885,-960 JP8.2
  Top Layer w9: 941.47,-298.5 1035.37,-298.5 1240,-503.13 1240,-755 1460.5,-975.5 1858.03,-975.5
A3TXC_N: C32.1 U1.32 | length 850.9
  Top Layer w6: U1.32 131.14,-127.95 131.48,-127.61 162.96,-127.61 ; 780.43,-317.5 794.5,-317.5 810,-333 C32.1
  Top Layer w9: 162.96,-127.61 215.74,-127.61 275,-186.87 275,-235 357.5,-317.5 781.88,-317.5
A3TXC_P: C31.1 U1.33 | length 849.5
  Top Layer w6: U1.33 131.14,-108.27 131.48,-108.61 162.96,-108.61 ; 781.88,-298.5 795.5,-298.5 811,-283 C31.1
  Top Layer w9: 162.96,-108.61 223.61,-108.61 294,-179 294,-227.13 365.37,-298.5 781.88,-298.5
A4: SW1.8 U1.25 | length 1639.5
  Top Layer w9: v1@9.84,-369.84 U1.25 ; v1(275,835) SW1.8
  Top Layer w11: v1(10,-370) v1@10,-369.84
  Bottom Layer w9: v1(10,-370) 185,-370 295,-260 295,270 275,290 v1(275,835)
B0RX_N: C2.2 JP2.5 | length 1518.9
  Top Layer w6: C2.2 909,348 924.5,332.5 939.29,332.5 ; 1858.03,1034.5 1869.5,1034.5 1885,1050 JP2.5
  Top Layer w9: 939.29,332.5 1027.5,332.5 1220,525 1220,815 1439.5,1034.5 1858.03,1034.5
B0RX_P: C4.2 JP2.6 | length 1516.7
  Top Layer w6: C4.2 908,298 923.5,313.5 937.12,313.5 ; 1859.11,1015.5 1869.5,1015.5 1885,1000 JP2.6
  Top Layer w9: 939.29,313.5 1035.37,313.5 1239,517.13 1239,807.13 1447.37,1015.5 1859.11,1015.5
B0RXC_N: C2.1 U1.46 | length 867.7
  Top Layer w6: U1.46 131.14,147.64 131.48,147.3 162.96,147.3 ; 781.88,332.5 795.5,332.5 811,348 C2.1
  Top Layer w9: 162.96,147.3 225.42,147.3 281,202.87 281,287.87 325.63,332.5 780.43,332.5
B0RXC_P: C4.1 U1.45 | length 869.1
  Top Layer w6: U1.45 131.14,127.95 131.48,128.3 162.96,128.3 ; 780.43,313.5 794.5,313.5 810,298 C4.1
  Top Layer w9: 162.96,128.3 233.3,128.3 300,195 300,280 333.5,313.5 780.43,313.5
B0TX_N: C17.1 JP1.5 | length 1526.5
  Top Layer w6: v1(-1885,1050) -1865,1050 -1849.5,1034.5 -1834.84,1034.5 ; -947,311 -932,311 -917,326 C17.1
  Top Layer w9: -1834.84,1034.5 -1569.5,1034.5 -1390,855 -1390,595 -1106,311 -947,311
  Bottom Layer w6: JP1.5 v1(-1885,1050)
B0TX_P: C18.1 JP1.6 | length 1527.5
  Top Layer w6: v1(-1885,1000) -1865,1000 -1849.5,1015.5 -1833.73,1015.5 ; -948,292 -931,292 -916,277 C18.1
  Top Layer w9: -1833.73,1015.5 -1577.37,1015.5 -1409,847.13 -1409,587.13 -1113.87,292 -947,292
  Bottom Layer w6: JP1.6 v1(-1885,1000)
B0TXC_N: C17.2 U1.4 | length 846.8
  Top Layer w6: C17.2 -814,326 -799,311 -779,311 ; -165.14,127.61 -131.88,127.61 -131.54,127.95 U1.4@-98.82,127.95
  Top Layer w9: -779,311 -361,311 -275,225 -275,181.87 -220.74,127.61 -165.14,127.61
B0TXC_P: C18.2 U1.5 | length 845.8
  Top Layer w6: C18.2 -812,277 -797,292 -780,292 ; -166.3,108.61 -131.88,108.61 -131.54,108.27 U1.5@-98.82,108.27
  Top Layer w9: -779,292 -368.87,292 -294,217.13 -294,174 -228.61,108.61 -166.3,108.61
B1RX_N: C6.2 JP4.5 | length 1155.2
  Top Layer w6: C6.2 912,96 927.5,80.5 941.47,80.5 ; 1858.03,314.5 1869.5,314.5 1885,330 JP4.5
  Top Layer w9: 941.47,80.5 1065.5,80.5 1299.5,314.5 1858.03,314.5
B1RX_P: C8.2 JP4.6 | length 1155.2
  Top Layer w6: C8.2 910,46 925.5,61.5 941.47,61.5 ; 1859.11,295.5 1869.5,295.5 1885,280 JP4.6
  Top Layer w9: 941.47,61.5 1073.37,61.5 1307.37,295.5 1859.11,295.5
B1RXC_N: C6.1 U1.41 | length 755.7
  Top Layer w6: U1.41 131.14,49.21 131.48,48.87 162.96,48.87 ; 781.88,80.5 795.5,80.5 811,96 C6.1
  Top Layer w9: 162.96,48.87 282,48.87 313.63,80.5 781.88,80.5
B1RXC_P: C8.1 U1.40 | length 757.2
  Top Layer w6: U1.40 131.14,29.53 131.48,29.87 162.96,29.87 ; 780.43,61.5 794.5,61.5 810,46 C8.1
  Top Layer w9: 162.96,29.87 289.87,29.87 321.5,61.5 781.88,61.5
B1TX_N: C19.1 JP3.5 | length 1174.2
  Top Layer w6: v1(-1885,320) -1865,320 -1849.5,304.5 -1834.84,304.5 ; -948,64.5 -930.5,64.5 -915,80 C19.1
  Top Layer w9: -1834.84,304.5 -1394.5,304.5 -1154.5,64.5 -948,64.5
  Bottom Layer w6: JP3.5 v1(-1885,320)
B1TX_P: C20.1 JP3.6 | length 1174.2
  Top Layer w6: v1(-1885,270) -1865,270 -1849.5,285.5 -1833.73,285.5 ; -948,45.5 -930.5,45.5 -915,30 C20.1
  Top Layer w9: -1833.73,285.5 -1402.37,285.5 -1162.37,45.5 -948,45.5
  Bottom Layer w6: JP3.6 v1(-1885,270)
B1TXC_N: C19.2 U1.9 | length 760.4
  Top Layer w6: C19.2 -810,80 -794.5,64.5 -773,64.5 ; -165.14,29.18 -131.88,29.18 -131.54,29.53 U1.9@-98.82,29.53
  Top Layer w9: -773,64.5 -324.5,64.5 -289.18,29.18 -165.14,29.18
B1TXC_P: C20.2 U1.10 | length 759.4
  Top Layer w6: C20.2 -810,30 -794.5,45.5 -774,45.5 ; -165.07,10.18 -131.88,10.18 -131.54,9.84 U1.10@-98.82,9.84
  Top Layer w9: -773,45.5 -332.37,45.5 -297.06,10.18 -165.07,10.18
B2RX_N: C10.2 JP6.5 | length 1152.3
  Top Layer w6: C10.2 910,-158 925.5,-173.5 944.38,-173.5 ; 1858.03,-400.5 1869.5,-400.5 1885,-385 JP6.5
  Top Layer w9: 944.38,-173.5 1063.5,-173.5 1290.5,-400.5 1567.27,-400.5 1858.03,-400.5
B2RX_P: C12.2 JP6.6 | length 1159.4
  Top Layer w6: C12.2 912,-208 927.5,-192.5 943.65,-192.5 ; 1859.11,-419.5 1869.5,-419.5 1885,-435 JP6.6
  Top Layer w9: 944.38,-192.5 1055.63,-192.5 1282.63,-419.5 1567.27,-419.5 ; 1559.4,-419.5 1859.11,-419.5
B2RXC_N: C10.1 U1.36 | length 794
  Top Layer w6: U1.36 131.14,-49.21 131.48,-49.56 162.96,-49.56 ; 781.88,-173.5 795.5,-173.5 811,-158 C10.1
  Top Layer w9: 162.96,-49.56 239.56,-49.56 363.5,-173.5 781.88,-173.5
B2RXC_P: C12.1 U1.35 | length 795.4
  Top Layer w6: U1.35 131.14,-68.9 131.48,-68.56 162.96,-68.56 ; 780.43,-192.5 794.5,-192.5 810,-208 C12.1
  Top Layer w9: 162.96,-68.56 231.68,-68.56 355.63,-192.5 781.88,-192.5
B2TX_N: C23.1 JP5.5 | length 1175.2
  Top Layer w6: v1(-1885,-410) -1865,-410 -1849.5,-425.5 -1834.84,-425.5 ; -947,-185.5 -931.5,-185.5 -916,-170 C23.1
  Top Layer w9: -1834.84,-425.5 -1365.5,-425.5 -1125.5,-185.5 -946,-185.5
  Bottom Layer w6: JP5.5 v1(-1885,-410)
B2TX_P: C25.1 JP5.6 | length 1174.2
  Top Layer w6: v1(-1885,-460) -1865,-460 -1849.5,-444.5 -1833.73,-444.5 ; -946,-204.5 -930.5,-204.5 -915,-220 C25.1
  Top Layer w9: -1833.73,-444.5 -1357.63,-444.5 -1117.63,-204.5 -946,-204.5
  Bottom Layer w6: JP5.6 v1(-1885,-460)
B2TXC_N: C23.2 U1.14 | length 793.9
  Top Layer w6: C23.2 -810,-170 -794.5,-185.5 -773,-185.5 ; -164.37,-69.24 -131.88,-69.24 -131.54,-68.9 U1.14@-98.82,-68.9
  Top Layer w9: -773,-185.5 -382.37,-185.5 -266.11,-69.24 -164.37,-69.24
B2TXC_P: C25.2 U1.15 | length 793.9
  Top Layer w6: C25.2 -812,-220 -796.5,-204.5 -773,-204.5 ; -164.75,-88.24 -131.88,-88.24 -131.54,-88.58 U1.15@-98.82,-88.58
  Top Layer w9: -773,-204.5 -374.5,-204.5 -258.24,-88.24 -164.75,-88.24
B3RX_N: C14.2 JP8.5 | length 1534.4
  Top Layer w6: C14.2 909,-406 924.5,-421.5 941.47,-421.5 ; 1858.03,-1125.5 1869.5,-1125.5 1885,-1110 JP8.5
  Top Layer w9: 941.47,-421.5 1026.5,-421.5 1115,-510 1115,-825 1415.5,-1125.5 1858.03,-1125.5
B3RX_P: C16.2 JP8.6 | length 1534.4
  Top Layer w6: C16.2 907,-456 922.5,-440.5 941.47,-440.5 ; 1859.11,-1144.5 1869.5,-1144.5 1885,-1160 JP8.6
  Top Layer w9: 941.47,-440.5 1018.63,-440.5 1096,-517.87 1096,-832.87 1407.63,-1144.5 1859.11,-1144.5
B3RXC_N: C14.1 U1.31 | length 899.9
  Top Layer w6: U1.31 131.14,-147.64 131.48,-147.98 162.96,-147.98 ; 781.88,-421.5 795.5,-421.5 811,-406 C14.1
  Top Layer w9: 162.96,-147.98 182.98,-147.98 230,-195 230,-270 381.5,-421.5 781.88,-421.5
B3RXC_P: C16.1 U1.30 | length 901.3
  Top Layer w6: U1.30 131.14,-167.32 131.48,-166.98 162.96,-166.98 ; 780.43,-440.5 794.5,-440.5 810,-456 C16.1
  Top Layer w9: 162.96,-166.98 175.11,-166.98 211,-202.87 211,-277.87 373.63,-440.5 781.88,-440.5
B3TX_N: C27.1 JP7.5 | length 1542.3
  Top Layer w6: v1(-1885,-1135) -1865,-1135 -1849.5,-1150.5 -1834.84,-1150.5 ; -943,-427.5 -926.11,-427.5 -910.61,-412 C27.1
  Top Layer w9: -1834.84,-1150.5 -1465.5,-1150.5 -1174,-859 -1174,-572.13 -1029.37,-427.5 -943,-427.5
  Bottom Layer w6: JP7.5 v1(-1885,-1135)
B3TX_P: C28.1 JP7.6 | length 1542.3
  Top Layer w6: v1(-1885,-1185) -1865,-1185 -1849.5,-1169.5 -1833.73,-1169.5 ; -943,-446.5 -926.11,-446.5 -910.61,-462 C28.1
  Top Layer w9: -1833.73,-1169.5 -1457.63,-1169.5 -1155,-866.87 -1155,-580 -1021.5,-446.5 -943,-446.5
  Bottom Layer w6: JP7.6 v1(-1885,-1185)
B3TXC_N: C27.2 U1.19 | length 900.2
  Top Layer w6: C27.2 -812,-412 -796.5,-427.5 -771,-427.5 ; -163.21,-167.67 -131.88,-167.67 -131.54,-167.32 U1.19@-98.82,-167.32
  Top Layer w9: -771,-427.5 -369.37,-427.5 -219,-277.13 -219,-197.13 -189.54,-167.67 -163.21,-167.67
B3TXC_P: C28.2 U1.20 | length 900.2
  Top Layer w6: C28.2 -811,-462 -795.5,-446.5 -771,-446.5 ; -163.21,-186.67 -131.88,-186.67 -131.54,-187.01 U1.20@-98.82,-187.01
  Top Layer w9: -771,-446.5 -361.5,-446.5 -200,-285 -200,-205 -181.67,-186.67 -163.21,-186.67
GND: ?.0 C42.2 C43.2 C44.2 C45.1 C46.2 C47.2 C49.2 C51.2 C60.2 C61.2 C62.2 C63.2 C65.2 C66.2 C67.2 C68.2 C69.2 C70.2 C71.2 EC1.2 J2.5 JP1.1 JP1.4 JP1.7 JP2.1 JP2.4 JP2.7 JP3.1 JP3.4 JP3.7 JP4.1 JP4.4 JP4.7 JP5.1 JP5.4 JP5.7 JP6.1 JP6.4 JP6.7 JP7.1 JP7.4 JP7.7 JP8.1 JP8.4 JP8.7 JP9.4 pad.0 Q5.E Q6.E R9.1 R10.2 R21.2 SW1.9 SW1.10 SW1.11 SW1.12 SW1.13 SW1.14 SW1.15 SW1.16 U1.55 U1.56 U1.57 U2.2 | length 3512.3
  Top Layer w12: U1.56@-69.29,216.54 -69.29,184.29 v1(-33,148) ; U1.55@-49.61,216.54 -49.61,181.61 U1.57@-26,158
  Top Layer w20: v2(-869,-1000) C45.1 ; v2(-780,-1233) -780,-1170 -765,-1155 C46.2@-723.11,-1155 ; C51.2 v1(-780,1010) ; v2(-738,-1233) -738,-1169.89 C46.2@-723.11,-1155 ; v2(-693,-1233) -693,-1185.11 C46.2@-723.11,-1155 ; R21.2 v1(-679.97,999.97) ; v2(-652,-1233) C46.2@-652,-1170 ; SW1.16 v1(-75,1225) ; SW1.15 v1(-25,1225) ; SW1.14 v1(25,1225) ; SW1.13 v1(75,1225) ; SW1.12 v1(125,1225) ; J2.5@164,-1420 J2.5@255,-1420 ; J2.5@166,-1441 J2.5@243,-1441 ; J2.5@169,-1465 J2.5@246,-1465 ; J2.5@170,-1486 J2.5@251,-1486 ; SW1.11 v1(175,1225) ; SW1.10 v1(225,1225) ; v2(235,-1323) R9.1 ; SW1.9 v1(275,1225) ; v1(418,-611) Q6.E ; Q5.E v1(624,766) ; v1(1870,-1210) JP8.7 ; v1(1870,-1060) JP8.4 ; v1(1870,-485) JP6.7 ; v1(1870,-335) JP6.4 ; v1(1870,230) JP4.7 ; v1(1870,380) JP4.4 ; v1(1870,950) JP2.7 ; v1(1870,1100) JP2.4 ; JP8.1 v1(1990,-910) ; JP6.1 v1(1985,-185) ; JP4.1 v1(1990,530) ; JP2.1 v1(1985,1250)
  Bottom Layer w20: v1(-2005,-935) JP7.1 ; v1(-2005,-210) JP5.1 ; v1(-2005,520) JP3.1 ; v1(-2005,1250) JP1.1 ; JP7.7 v1(-1890,-1235) ; JP7.4 v1(-1890,-1085) ; JP5.7 v1(-1890,-510) ; JP5.4 v1(-1890,-360) ; JP3.7 v1(-1890,220) ; JP3.4 v1(-1890,370) ; JP1.7 v1(-1890,950) ; JP1.4 v1(-1890,1100) ; C69.2@-124,401 v1(-124,430) ; C69.2@-95,403 v1(-95,432) ; C63.2 -43.27,-108.27 v1(-34,-99) ; C62.2 -36.16,-9.84 ; C61.2 v1(-38.58,88.58) ; C60.2 -72.01,187.01 v1(-33,148) ; C65.2 -69.29,-179.29 v1(-36,-146) ; v1(24,-146) 65.01,-187.01 C66.2 ; v1(25,110) C70.2 ; v1(30,145) 59,174 C71.2 ; 37.84,9.84 C68.2@73.03,9.84 ; v1(39.58,-88.58) C67.2 ; v1(55,-1000) C49.2 ; v1(100,-990) R10.2
  other v2: 206,-1486 206,-1441
LB#: SW1.5 U1.28 | length 1394.8
  Top Layer w9: U1.28 68.9,-273.9 v1(85,-290) ; v1(125,835) SW1.5
  Bottom Layer w9: v1(85,-290) 150,-290 225,-215 225,220 125,320 v1(125,835)
MODE: SW1.1 U1.23 | length 1504.6
  Top Layer w9: v1(-75,835) SW1.1 ; U1.23 -29.53,-250.47 v1(-15,-265)
  Bottom Layer w9: v1(-75,835) -75,480 205,200 205,-200 140,-265 v1(-15,-265)
NetC43_1: C43.1 C44.1 C48.1 L1.2 L2.1 R7.1 R8.1 | length 100.6
  Bottom Layer w20: v1(-395,-1054.33) C48.1 ; v1(-395,-1004.33) R7.1 ; v1(-395,-959.33) R8.1
NetC48_2: C48.2 C49.1 R7.2 R8.2 R10.1 U2.4 | length 609.4
  Top Layer w20: U2.4 -25.5,-889.33 v3(-5,-889.33)
  Bottom Layer w20: R7.2 -120,-1004.33 v3(-5,-889.33) 25,-919.33 R10.1@100,-919.33 ; R8.2 -320.32,-1049.02 C48.2
NetC51_1: C51.1 Q7.G Q8.G R21.1 R22.1 | length 473.7
  Top Layer w20: C51.1@-779.05,929.05 R21.1 -679.97,849.97 -621.06,791.06 Q7.G -556.06,830 -493.94,830 Q8.G Q8.G@-455,805
NetD3_1: D3.1 D5.1 J2.1 | length 234.3
  Top Layer w20: J2.1@40,-1449.95 D3.1 ; D3.1@40.63,-1324.37 D5.1
NetD4_2: D4.2 R16.2 | length 98.4
  Top Layer w11: R16.2 D4.2@650.03,982.66
NetD5_2: D5.2 R9.2 | length 84.7
  Top Layer w20: D5.2@150.31,-1245.32 R9.2
NetD6_2: D6.2 R15.2 | length 75.4
  Top Layer w11: D6.2@414.61,-785 R15.2@490,-785
NetL1_1: L1.1 U2.5 | length 104.8
  Top Layer w20: L1.1@-201.73,-869.33 -173.73,-897.33 U2.5
NetQ5_B: Q5.B R18.2 | length 63.7
  Top Layer w11: R18.2 Q5.B@519.03,764.97
NetQ5_C: Q5.C R16.1 | length 93.5
  Top Layer w11: Q5.C R16.1@648.98,841
NetQ6_B: Q6.B R17.2 | length 56.7
  Top Layer w11: Q6.B@527.27,-612.27 R17.2
NetQ6_C: Q6.C R15.1 | length 57.6
  Top Layer w11: R15.1@488.52,-743.6 Q6.C
PD#: SW1.2 U1.51 | length 723.3
  Top Layer w9: SW1.2@-25,917.2 -25,790 29.53,735.47 U1.51
SCL: Q7.S R4.2 U1.53 | length 805.6
  Top Layer w9: Q7.S R4.2 -486.3,721.3 -9.84,244.84 U1.53
SCL_CONN: JP9.2 Q7.D R20.2 | length 280.6
  Top Layer w9: Q7.D -557.52,1122.48 JP9.2
SDA: Q8.S R5.2 U1.52 | length 736
  Top Layer w9: R5.2 Q8.S ; R5.2 -300,641.3 -300,570 9.84,260.16 U1.52
SDA_CONN: JP9.3 Q8.D R19.2 | length 278.5
  Top Layer w9: JP9.3 -417.52,1127.52 Q8.D
SIG_A: R18.1 U1.50 | length 675.6
  Top Layer w9: U1.50@48.82,216.53 48.82,254.21 453.65,659.05 R18.1
SIG_B: R17.1 U1.22 | length 867.2
  Top Layer w9: U1.22@-49.61,-216.53 -49.61,-365.39 155.05,-570.05 R17.1
pads on no net: ?. J2.2 J2.3 J2.4 J2.10 J2.11 JP1.0 JP2.0 JP3.0 JP4.0 JP5.0 JP6.0 JP7.0 JP8.0 SW1.3 SW1.4 U1.24 U1.54

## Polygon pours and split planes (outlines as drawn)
+5.0V on Top Layer "MidLayer1-No Net" (solid, remove dead copper, pour order 1002): -65,-1350 -65,-1300 -115,-1250 -115,-1100 -90,-1075 -90,-1035 -100,-1025 -125,-1025 -160,-1025 -190,-1055 -195,-1060 -195,-1240 -210,-1255 -285,-1255 -310,-1280 -310,-1430 -275,-1465 -210,-1465 -165,-1420 -120,-1375 -85,-1375 -65,-1355 -65,-1350
GND on Top Layer "MidLayer1-No Net" (solid, remove dead copper, pour order 1001): 20,-595 -600,-595 -600,-1785 20,-1785 20,-595
NetC43_1 on Top Layer "MidLayer1-No Net" (solid, remove dead copper, pour order 1000): -585,-665 -409.33,-665 -375,-699.33 -375,-1160 -380,-1165 -490,-1165 -510,-1145 -510,-935 -585,-860 -585,-665
NetL1_1 on Top Layer "MidLayer1-No Net" (solid, remove dead copper, pour order 1000): -90,-929.33 -150,-929.33 -175,-929.33 -200,-954.33 -240,-954.33 -240,-719.33 -225,-704.33 -110,-704.33 -90,-724.33 -90,-929.33
+1V2 on Top Layer "MidLayer1-No Net" (solid, remove dead copper, pour order 1003): -895,-935 -850,-935 -815,-970 -625,-970 -605,-950 -605,-720 -620,-705 -870,-705 -895,-730 -895,-935
GND on Bottom Layer "MidLayer1-No Net" (solid, remove dead copper, pour order 1003): 195,-595 -605,-595 -605,-1785 195,-1785 195,-595
+1V2 on Bottom Layer "Top Layer-No Net" (solid, remove dead copper, pour order 1000): -795.56,-810 -805,-820 -805,-870 -795.56,-880 -644.44,-880 -635,-870 -635,-820 -644.44,-810 -795.56,-810
GND on InternalPlane1 (split plane): 2178.48,1778.35 2201.56,1773.76 2223.84,1766.19 2244.94,1755.78 2264.51,1742.71 2282.2,1727.2 2297.71,1709.51 2310.79,1689.94 2321.19,1668.84 2328.76,1646.56 2333.35,1623.48 2334.82,1601.05 2334.61,1600 2334.61,-1600 2334.82,-1601.05 2333.35,-1623.48 2328.76,-1646.56 2321.19,-1668.84 2310.79,-1689.94 2297.71,-1709.51 2282.2,-1727.2 2264.51,-1742.71 2244.94,-1755.79 2223.84,-1766.19 2201.56,-1773.76 2178.48,-1778.35 2156.05,-1779.82 2155,-1779.61 -94.8,-1779.61 -94.8,-1439.22 42.21,-1302.21 44.42,-1298.9 45.2,-1295 45.2,-690 44.42,-686.1 42.21,-682.79 38.9,-680.58 35,-679.8 -605,-679.8 -608.9,-680.58 -612.21,-682.79 -614.42,-686.1 -615.2,-690 -615.2,-1225.78 -727.21,-1337.79 -729.42,-1341.1 -730.2,-1345 -730.2,-1779.61 -2175,-1779.61 -2176.05,-1779.82 -2198.48,-1778.35 -2221.56,-1773.76 -2243.84,-1766.19 -2264.94,-1755.79 -2284.51,-1742.71 -2302.2,-1727.2 -2317.71,-1709.51 -2330.79,-1689.94 -2341.19,-1668.84 -2348.76,-1646.56 -2353.35,-1623.48 -2354.82,-1601.05 -2354.61,-1600 -2354.61,1600 -2354.82,1601.05 -2353.35,1623.48 -2348.76,1646.56 -2341.19,1668.84 -2330.79,1689.94 -2317.71,1709.51 -2302.2,1727.2 -2284.51,1742.71 -2264.94,1755.78 -2243.84,1766.19 -2221.56,1773.76 -2198.48,1778.35 -2176.05,1779.82 -2175,1779.61 2155,1779.61 2156.05,1779.82
GND on InternalPlane1 (split plane): -205.2,-1539.8 -519.8,-1539.8 -519.8,-1239.22 -390.78,-1110.2 -345,-1110.2 -341.1,-1109.42 -337.79,-1107.21 -335.58,-1103.9 -334.8,-1100 -334.8,-1005.2 -205.2,-1005.2
+3V3 on InternalPlane2 (split plane): 2178.48,1778.35 2201.56,1773.76 2223.84,1766.19 2244.94,1755.78 2264.51,1742.71 2282.2,1727.2 2297.71,1709.51 2310.79,1689.94 2321.19,1668.84 2328.76,1646.56 2333.35,1623.48 2334.82,1601.05 2334.61,1600 2334.61,-1600 2334.82,-1601.05 2333.35,-1623.48 2328.76,-1646.56 2321.19,-1668.84 2310.79,-1689.94 2297.71,-1709.51 2282.2,-1727.2 2264.51,-1742.71 2244.94,-1755.79 2223.84,-1766.19 2201.56,-1773.76 2178.48,-1778.35 2156.05,-1779.82 2155,-1779.61 -2175,-1779.61 -2176.05,-1779.82 -2198.48,-1778.35 -2221.56,-1773.76 -2243.84,-1766.19 -2264.94,-1755.79 -2284.51,-1742.71 -2302.2,-1727.2 -2317.71,-1709.51 -2330.79,-1689.94 -2341.19,-1668.84 -2348.76,-1646.56 -2353.35,-1623.48 -2354.82,-1601.05 -2354.61,-1600 -2354.61,1600 -2354.82,1601.05 -2353.35,1623.48 -2348.76,1646.56 -2341.19,1668.84 -2330.79,1689.94 -2317.71,1709.51 -2302.2,1727.2 -2284.51,1742.71 -2264.94,1755.78 -2243.84,1766.19 -2221.56,1773.76 -2198.48,1778.35 -2176.05,1779.82 -2175,1779.61 2155,1779.61 2156.05,1779.82
+1V2 on InternalPlane2 (split plane): 589.8,-489.8 -145,-489.8 -148.9,-490.58 -152.21,-492.79 -154.42,-496.1 -155.2,-500 -155.2,-1089.8 -949.8,-1089.8 -949.8,689.8 589.8,689.8

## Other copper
Top Layer:
  pour cut-out: -52.15,-718.48 -52.15,-697.85 -85,-665 -325,-665 -355,-635 -605,-635 -605,-661.1 -401.27,-661.1 -365.24,-697.12 -103.37,-697.12 -81.62,-718.87 -80.66,-717.91 -51.57,-717.91
  pour cut-out: -75.87,-718.48 -52.15,-718.48 -51,-717.33 -51,-937.33 -73.72,-937.33 -75.87,-935.19
  text "TOP LAYER" at 3686,-1360 h80
  text "1" at 4336,-1490 h80
Bottom Layer:
  text "BOTTOM LAYER" at 3686,-1360 h80
  text "4" at 4336,-1490 h80
  text "1140DB158" at 1870,-1705 h60
InternalPlane1 (plane layer: these items are gaps in the copper):
  region: -345,-995 -345,-690 35,-690 35,-1295 -105,-1435 -105,-1795 -530,-1795 -530,-1550 -195,-1550 -195,-995
  region: -720,-1795 -720,-1345 -605,-1230 -605,-690 -345,-690 -345,-1100 -395,-1100 -530,-1235 -530,-1795
  region: -246,-934.83 -246,-719.83 -231,-704.83 -196,-704.83 -151,-749.83 -151,-929.83 -181,-959.83 -221,-959.83
  lines w20: -720,-1795 -720,-1345 -605,-1230 -605,-690 35,-690 35,-1295 -105,-1435 -105,-1795 ; -530,-1550 -530,-1235 -395,-1100 -345,-1100 -345,-995 -195,-995 -195,-1550 -530,-1550
  text "POWER PLANE LAYER" at 3686,-1360 h80
  text "2" at 4336,-1490 h80
InternalPlane2 (plane layer: these items are gaps in the copper):
  lines w20: -960,-1100 -145,-1100 -145,-500 600,-500 600,700 -960,700 -960,-1100
  text "GND PLANE LAYER" at 3686,-1360 h80
  text "3" at 4336,-1490 h80

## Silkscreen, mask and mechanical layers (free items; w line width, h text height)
Top Overlay:
  rectangle: 525,-1785 1400,-1600
  lines w8: -662.5,1022.5 -607.5,1022.5 -635,1050 -662.5,1022.5
  text "+3V3" at -660,1435 h60 r270
  text "JP1" at -1870,1430 h60 r270
  text "HOST" at -1800,1430 h60 r270
  text "GND" at -350,1430 h60 r270
  text "DEVICE" at 1760,1430 h60 r270
  text "SDA" at -445,1425 h60 r270
  text "SCL" at -550,1415 h60 r270
  text "MODE" at -95,800 h60 r270
  text "PD#" at -45,800 h60 r270
  text "LB#" at 110,800 h60 r270
  text "A1" at 160,800 h60 r270
  text "A0" at 210,800 h60 r270
  text "A4" at 260,800 h60 r270
  text "DEVICE" at 1760,710 h60 r270
  text "HOST" at -1805,700 h60 r270
  text "JP3" at -1870,695 h60 r270
  text "DEVICE" at 1760,0 h60 r270
  text "JP5" at -1865,-30 h60 r270
  text "HOST" at -1800,-30 h60 r270
  text "DEVICE" at 1755,-730 h60 r270
  text "HOST" at -1795,-750 h60 r270
  text "JP7" at -1875,-755 h60 r270
  text "TOP SILKSCREEN LAYER" at 3686,-1360 h80
  text "PI2EQX6874ZFE SATA3.0/SAS2.0 ReDriver" at 380,-1390 h80
  text "P/N:PI2EQX6874ZFE SATA CONN  EVB" at 380,-1480 h80
  text "5" at 4336,-1490 h80
  text "REV.A" at 380,-1570 h80
  text "Date:2011.10.11" at 675,-1570 h80
  text "S/N:" at 375,-1710 h80
Bottom Overlay:
  text "HOST" at -1760,1430 h60 r90
  text "HOST" at -1765,700 h60 r90
  text "HOST" at -1760,-30 h60 r90
  text "HOST" at -1760,-750 h60 r90
  text "BOTTOM SILKSCREEN LAYER" at 3686,-1360 h80
  text "6" at 4336,-1490 h80
Top Paste:
  text "TOP PASTE LAYER" at 3686,-1360 h80
  text "TOP PASTE LAYER" at 3686,-1360 h80
  text "TP" at 4316,-1490 h80
Bottom Paste:
  text "BOTTOM PASTE LAYER" at 3686,-1360 h80
  text "BOTTOM PASTE LAYER" at 3686,-1360 h80
  text "BP" at 4316,-1490 h80
Top Solder:
  text "TOP SOLDER LAYER" at 3686,-1360 h80
  text "7" at 4336,-1490 h80
Bottom Solder:
  text "BOTTOM SOLDER LAYER" at 3686,-1360 h80
  text "8" at 4336,-1490 h80
Drill Guide:
  text "DRILL GUIDE LAYER" at 3686,-1360 h80
  text "10" at 4316,-1490 h80
Mechanical 1:
  lines w8: -2375,-1600 ccw(c-2175,-1600) -2175,-1800 2155,-1800 ccw(c2155,-1600) 2355,-1600 2355,1600 ccw(c2155,1600) 2155,1800 -2175,1800 ccw(c-2175,1600) -2375,1600 -2375,-1600
  lines w10: 3656,-1400 3656,-1010 ; 4056,-1530 4056,-1400 ; 4181,-1270 4181,-1140 ; 4876,-1270 4876,-1140
  lines w12: 3136,-1400 5695,-1400 ; 3136,-1270 5695,-1270 ; 3136,-1140 5695,-1140 ; 3136,-1010 5695,-1010 ; 3136,-950 3875,-950 ; 3136,-900 3795,-900 ; 3136,-850 3875,-850 ; 4676,-950 5695,-950 ; 4676,-850 5695,-850 ; 4766,-900 5695,-900
  lines w15: 3136,-1530 5695,-1530 5695,-780 3136,-780 3136,-1530
  text "Pericom" at 4005,-950 h180
  text "PCB NAME" at 3176,-1100 h60
  text "PI2EQX6874ZFE SAS ReDriver  EVB" at 3690,-1105 h80
  text "Rev.A" at 5495,-1105 h80
  text "Drawn by" at 4315,-1225 h60
  text "DATE" at 3266,-1230 h60
  text "10/11/2011" at 3676,-1230 h80
  text "Haojie Ci" at 5035,-1235 h80
  text "TITLE" at 3246,-1360 h60
  text "SHEET NUMBER" at 3256,-1490 h60
  text "OF       10" at 4556,-1490 h80
Drill Drawing:
  lines w10: 3646,180 3646,670 ; 3696,-450 3906,-450 ; 3696,-110 3906,-110 ; 3776,-390 3796,-450 ; 3776,-170 3796,-110 ; 3796,-340 3796,-450 ; 3796,-220 3796,-110 ; 3816,-390 3796,-450 ; 3816,-170 3796,-110 ; 4006,180 4006,670 ; 4916,180 4916,670 ; 6056,180 6056,670 ; 3996,-450 3996,-400 5036,-400 5036,-450 3996,-450 ; 3996,-359 3996,-309 5036,-309 5036,-359 3996,-359 ; 3996,-259 3996,-209 5036,-209 5036,-259 3996,-259 ; 3996,-160 5036,-160 5036,-110 3996,-110 3996,-160
  lines w12: 3136,310 6656,310 ; 3136,440 6656,440
  lines w15: 3136,180 3136,670 6656,670 6656,180 3136,180
  text "IMPEDANCE CHART" at 3136,700 h100
  text "TRACE" at 3686,560 h60
  text "SINGLE-ENDED" at 4036,560 h60
  text "DIFFERENTIAL-ENDED" at 4976,560 h60
  text "LAYER(S)" at 3176,520 h60
  text "TOLERANCE" at 6096,520 h60
  text "TYPE" at 3686,480 h60
  text "IMPEDANCE REQ'D" at 4036,480 h60
  text "IMPEDANCE REQ'D" at 4976,480 h60
  text "--" at 4446,360 h80
  text "+/- 10%" at 6236,360 h80
  text "1" at 3366,350 h80
  text "9/10/9mil" at 3686,350 h80
  text "100ohm" at 5356,350 h80
  text "4" at 3366,220 h80
  text "9/10/9mil" at 3686,220 h80
  text "--" at 4446,220 h80
  text "100ohm" at 5356,220 h80
  text "+/- 10%" at 6236,220 h80
  text "LAYER1 SIGNAL" at 5076,-160 h80
  text "LAYER2 GROUND PLANE" at 5075,-250 h80
  text "THICKNESS is 1.6mm" at 3176,-300 h80
  text "LAYER3 SPLIT PWR PLANE" at 5075,-360 h80
  text "LAYER4 SIGNAL" at 5076,-450 h80
  text "DRILL DRAWING LAYER" at 3686,-1360 h80
  text "9" at 4336,-1490 h80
